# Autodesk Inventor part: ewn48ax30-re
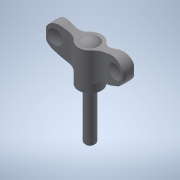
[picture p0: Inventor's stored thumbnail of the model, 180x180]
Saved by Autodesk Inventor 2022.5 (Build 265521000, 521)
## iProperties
Created: 2016-12
Part Number: ewn48ax30-re
Material: 一般
Document SubType Name: Modeling
Designer: imaocorp
Density: 1 g/cm^3
Appearance: 既定
Author: imaocorp
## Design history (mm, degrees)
node "ewn48ax30-re.x_t1"
node "ewn48ax30-re"
node "Base1"
